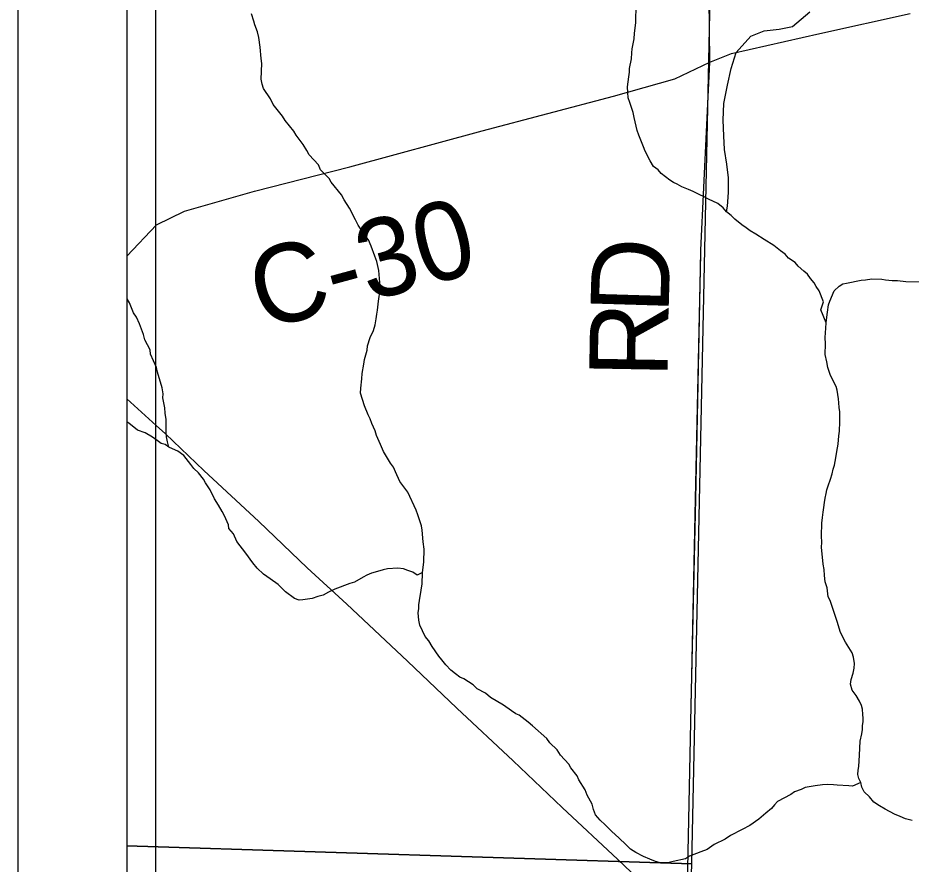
# Model space of a CAD drawing. Extents: x 0 to 34, y -2.3 to 22.
# Drawn here: x 2 to 2.648, y 15.492 to 16.107 of the extents above; entities that cross this region are included whole.
import ezdxf

# ---------------------------------------------------------------- set-up
doc = ezdxf.new("R2010")
doc.units = 0
for name, color, linetype in [('GM_X_County', 7, 'Continuous'), ('GM_X_County_Road', 7, 'Continuous'), ('GM_X_County_Road_Text', 7, 'Continuous'), ('GM_X_Minor_River', 7, 'Continuous'), ('GM_X_Section', 7, 'Continuous'), ('GM_X_State_Route', 7, 'Continuous'), ('GM_X_Township', 7, 'Continuous'), ('GM_X_Township_Road', 7, 'Continuous'), ('GM_X_Township_Road_Text', 7, 'Continuous'), ('SH_Data', 7, 'Continuous')]:
    doc.layers.add(name, color=color, linetype=linetype)

msp = doc.modelspace()

# ---------------------------------------------------------------- linework, layer by layer
at = {"layer": 'GM_X_County'}
msp.add_line((2.07917, 20.89939), (2.07917, 14.49705), dxfattribs=at)
at = {"layer": 'GM_X_County_Road'}
for p, q in [((2.58209, 16.09537), (2.64769, 16.10984)), ((2.51807, 16.0809), (2.58209, 16.09537)), ((2.50234, 16.0746), (2.51807, 16.0809)), ((2.47701, 16.06249), (2.50234, 16.0746)), ((2.43234, 16.04975), (2.47701, 16.06249)), ((2.33701, 16.02474), (2.43234, 16.04975)), ((2.24106, 15.99863), (2.33701, 16.02474)), ((2.17184, 15.98085), (2.24106, 15.99863)), ((2.12104, 15.96622), (2.17184, 15.98085)), ((2.10074, 15.95631), (2.12104, 15.96622)), ((2.07917, 15.93367), (2.10074, 15.95631))]:
    msp.add_line(p, q, dxfattribs=at)
at = {"layer": 'GM_X_Minor_River'}
for p, q in [((2.44859, 16.10618), (2.44901, 16.12099)), ((2.17141, 16.10421), (2.16967, 16.10958)), ((2.56232, 16.10048), (2.5748, 16.11115)), ((2.17209, 16.10153), (2.17141, 16.10421)), ((2.17385, 16.09654), (2.17209, 16.10153)), ((2.44752, 16.09558), (2.4485, 16.10315)), ((2.4485, 16.10315), (2.44859, 16.10618)), ((2.17487, 16.09233), (2.17385, 16.09654)), ((2.4474, 16.0914), (2.44752, 16.09558)), ((2.53209, 16.09338), (2.54171, 16.09728)), ((2.54171, 16.09728), (2.55276, 16.09848)), ((2.55276, 16.09848), (2.56232, 16.10048)), ((2.17581, 16.08546), (2.17487, 16.09233)), ((2.44605, 16.08423), (2.4474, 16.0914)), ((2.52148, 16.08152), (2.53209, 16.09338)), ((2.17671, 16.07708), (2.17581, 16.08546)), ((2.44558, 16.0812), (2.44605, 16.08423)), ((2.51772, 16.06985), (2.52148, 16.08152)), ((2.17699, 16.07365), (2.17671, 16.07708)), ((2.44411, 16.06985), (2.44546, 16.07703)), ((2.44546, 16.07703), (2.44558, 16.0812)), ((2.17666, 16.06226), (2.17699, 16.07365)), ((2.44404, 16.06719), (2.44411, 16.06985)), ((2.51509, 16.05775), (2.51772, 16.06985)), ((2.17731, 16.05845), (2.17666, 16.06226)), ((2.44259, 16.0566), (2.44356, 16.06379)), ((2.44356, 16.06379), (2.44404, 16.06719)), ((2.17836, 16.05538), (2.17731, 16.05845)), ((2.18347, 16.048), (2.17836, 16.05538)), ((2.44285, 16.05241), (2.44259, 16.0566)), ((2.51242, 16.04452), (2.51509, 16.05775)), ((2.44312, 16.0486), (2.44285, 16.05241)), ((2.18525, 16.04377), (2.18347, 16.048)), ((2.19222, 16.03521), (2.18525, 16.04377)), ((2.44416, 16.04516), (2.44312, 16.0486)), ((2.44661, 16.03786), (2.44416, 16.04516)), ((2.51206, 16.03236), (2.51242, 16.04452)), ((2.44727, 16.03443), (2.44661, 16.03786)), ((2.19403, 16.03211), (2.19222, 16.03521)), ((2.20027, 16.02433), (2.19403, 16.03211)), ((2.44965, 16.02486), (2.44727, 16.03443)), ((2.51249, 16.02094), (2.51206, 16.03236)), ((2.20209, 16.02162), (2.20027, 16.02433)), ((2.45069, 16.02141), (2.44965, 16.02486)), ((2.20721, 16.01463), (2.20209, 16.02162)), ((2.45425, 16.01294), (2.45069, 16.02141)), ((2.51296, 16.01104), (2.51249, 16.02094)), ((2.20975, 16.01037), (2.20721, 16.01463)), ((2.21156, 16.00728), (2.20975, 16.01037)), ((2.4553, 16.00987), (2.45425, 16.01294)), ((2.51455, 16.00035), (2.51296, 16.01104)), ((2.21819, 15.99986), (2.21156, 16.00728)), ((2.4589, 16.00293), (2.4553, 16.00987)), ((2.21961, 15.9964), (2.21819, 15.99986)), ((2.46144, 15.99867), (2.4589, 16.00293)), ((2.46479, 15.99629), (2.46144, 15.99867)), ((2.51578, 15.99042), (2.51455, 16.00035)), ((2.22589, 15.99014), (2.21961, 15.9964)), ((2.46699, 15.99357), (2.46479, 15.99629)), ((2.47332, 15.98882), (2.46699, 15.99357)), ((2.22733, 15.98743), (2.22589, 15.99014)), ((2.23504, 15.97809), (2.22733, 15.98743)), ((2.47593, 15.98722), (2.47332, 15.98882)), ((2.47856, 15.98601), (2.47593, 15.98722)), ((2.48192, 15.98401), (2.47856, 15.98601)), ((2.4868, 15.98196), (2.48192, 15.98401)), ((2.51584, 15.97977), (2.51578, 15.99042)), ((2.23684, 15.97461), (2.23504, 15.97809)), ((2.49019, 15.98072), (2.4868, 15.98196)), ((2.49506, 15.9783), (2.49019, 15.98072)), ((2.49769, 15.97708), (2.49506, 15.9783)), ((2.51518, 15.9699), (2.51584, 15.97977)), ((2.24085, 15.96842), (2.23684, 15.97461)), ((2.50143, 15.97507), (2.49769, 15.97708)), ((2.50818, 15.97183), (2.50143, 15.97507)), ((2.51189, 15.96868), (2.50818, 15.97183)), ((2.24516, 15.95993), (2.24085, 15.96842)), ((2.51447, 15.96594), (2.51189, 15.96868)), ((2.51447, 15.96594), (2.51518, 15.9699)), ((2.51781, 15.96318), (2.51447, 15.96594)), ((2.24695, 15.95608), (2.24516, 15.95993)), ((2.52039, 15.96045), (2.51781, 15.96318)), ((2.5256, 15.95649), (2.52039, 15.96045)), ((2.25205, 15.94833), (2.24695, 15.95608)), ((2.52857, 15.95412), (2.5256, 15.95649)), ((2.53156, 15.95214), (2.52857, 15.95412)), ((2.53567, 15.94973), (2.53156, 15.95214)), ((2.25463, 15.94559), (2.25205, 15.94833)), ((2.2564, 15.94098), (2.25463, 15.94559)), ((2.54164, 15.94575), (2.53567, 15.94973)), ((2.54873, 15.94136), (2.54164, 15.94575)), ((2.25923, 15.93368), (2.2564, 15.94098)), ((2.55356, 15.93742), (2.54873, 15.94136)), ((2.26064, 15.92984), (2.25923, 15.93368)), ((2.55691, 15.93504), (2.55356, 15.93742)), ((2.55949, 15.93231), (2.55691, 15.93504)), ((2.56434, 15.92912), (2.55949, 15.93231)), ((2.26197, 15.92334), (2.26064, 15.92984)), ((2.56655, 15.9264), (2.56434, 15.92912)), ((2.57062, 15.92285), (2.56655, 15.9264)), ((2.26286, 15.91457), (2.26197, 15.92334)), ((2.57322, 15.9205), (2.57062, 15.92285)), ((2.57541, 15.91739), (2.57322, 15.9205)), ((2.26265, 15.90736), (2.26286, 15.91457)), ((2.57798, 15.91428), (2.57541, 15.91739)), ((2.57942, 15.91158), (2.57798, 15.91428)), ((2.59616, 15.91184), (2.59887, 15.91366)), ((2.59887, 15.91366), (2.60154, 15.91396)), ((2.60154, 15.91396), (2.61225, 15.91629)), ((2.61225, 15.91629), (2.6153, 15.91658)), ((2.6153, 15.91658), (2.61988, 15.91721)), ((2.61988, 15.91721), (2.62709, 15.91699)), ((2.62709, 15.91699), (2.62974, 15.91653)), ((2.62974, 15.91653), (2.63467, 15.916)), ((2.63467, 15.916), (2.63847, 15.91589)), ((2.63847, 15.91589), (2.64453, 15.91533)), ((2.64453, 15.91533), (2.65783, 15.91493)), ((2.26218, 15.90434), (2.26265, 15.90736)), ((2.58161, 15.90847), (2.57942, 15.91158)), ((2.5848, 15.9004), (2.58161, 15.90847)), ((2.58938, 15.90102), (2.59264, 15.90852)), ((2.59264, 15.90852), (2.59616, 15.91184)), ((2.07929, 15.90259), (2.07917, 15.90274)), ((2.08111, 15.89987), (2.07929, 15.90259)), ((2.08394, 15.89257), (2.08111, 15.89987)), ((2.26114, 15.89449), (2.2617, 15.90093)), ((2.2617, 15.90093), (2.26218, 15.90434)), ((2.58293, 15.89466), (2.5848, 15.9004)), ((2.58854, 15.89839), (2.58938, 15.90102)), ((2.26067, 15.89147), (2.26114, 15.89449)), ((2.58664, 15.88515), (2.58293, 15.89466)), ((2.58763, 15.8931), (2.58854, 15.89839)), ((2.08613, 15.88947), (2.08394, 15.89257)), ((2.08827, 15.88446), (2.08613, 15.88947)), ((2.25931, 15.88391), (2.26019, 15.88806)), ((2.26019, 15.88806), (2.26067, 15.89147)), ((2.58664, 15.88515), (2.58714, 15.88931)), ((2.58714, 15.88931), (2.58763, 15.8931)), ((2.09108, 15.87678), (2.08827, 15.88446)), ((2.25805, 15.87977), (2.25931, 15.88391)), ((2.58595, 15.87453), (2.58653, 15.88135)), ((2.58653, 15.88135), (2.58664, 15.88515)), ((2.09211, 15.87295), (2.09108, 15.87678)), ((2.25392, 15.8685), (2.25562, 15.87453)), ((2.25562, 15.87453), (2.25805, 15.87977)), ((2.5862, 15.86997), (2.58595, 15.87453)), ((2.09608, 15.86562), (2.09211, 15.87295)), ((2.25345, 15.86547), (2.25392, 15.8685)), ((2.58598, 15.86238), (2.5862, 15.86997)), ((2.09638, 15.86257), (2.09608, 15.86562)), ((2.10066, 15.85294), (2.09638, 15.86257)), ((2.25174, 15.85868), (2.25345, 15.86547)), ((2.58735, 15.85702), (2.58598, 15.86238)), ((2.24992, 15.84848), (2.25126, 15.85528)), ((2.25126, 15.85528), (2.25174, 15.85868)), ((2.58799, 15.85282), (2.58735, 15.85702)), ((2.10132, 15.8495), (2.10066, 15.85294)), ((2.10479, 15.838), (2.10132, 15.8495)), ((2.24981, 15.84469), (2.24992, 15.84848)), ((2.58974, 15.84783), (2.58799, 15.85282)), ((2.5908, 15.84514), (2.58974, 15.84783)), ((2.24885, 15.83788), (2.24981, 15.84469)), ((2.59405, 15.83896), (2.5908, 15.84514)), ((2.10543, 15.83381), (2.10479, 15.838)), ((2.24875, 15.83408), (2.24885, 15.83788)), ((2.59473, 15.83628), (2.59405, 15.83896)), ((2.59569, 15.83018), (2.59473, 15.83628)), ((2.10534, 15.83077), (2.10543, 15.83381)), ((2.10665, 15.82351), (2.10534, 15.83077)), ((2.25152, 15.82488), (2.24875, 15.83408)), ((2.59598, 15.82713), (2.59569, 15.83018)), ((2.10692, 15.81971), (2.10665, 15.82351)), ((2.25437, 15.81834), (2.25152, 15.82488)), ((2.59627, 15.8237), (2.59598, 15.82713)), ((2.59656, 15.82065), (2.59627, 15.8237)), ((2.10755, 15.81513), (2.10692, 15.81971)), ((2.25581, 15.81564), (2.25437, 15.81834)), ((2.25686, 15.81219), (2.25581, 15.81564)), ((2.59673, 15.81343), (2.59656, 15.82065)), ((2.08048, 15.81252), (2.07917, 15.81327)), ((2.0868, 15.80739), (2.08048, 15.81252)), ((2.10776, 15.80942), (2.10755, 15.81513)), ((2.10766, 15.80601), (2.10776, 15.80942)), ((2.25936, 15.80679), (2.25686, 15.81219)), ((2.59653, 15.8066), (2.59673, 15.81343)), ((2.09244, 15.80532), (2.0868, 15.80739)), ((2.09767, 15.80213), (2.09244, 15.80532)), ((2.10795, 15.80258), (2.10766, 15.80601)), ((2.1086, 15.79876), (2.10795, 15.80258)), ((2.2604, 15.80334), (2.25936, 15.80679)), ((2.26325, 15.7968), (2.2604, 15.80334)), ((2.5955, 15.79713), (2.59605, 15.80319)), ((2.59605, 15.80319), (2.59653, 15.8066)), ((2.10102, 15.79975), (2.09767, 15.80213)), ((2.104, 15.79776), (2.10102, 15.79975)), ((2.10702, 15.79691), (2.104, 15.79776)), ((2.10963, 15.79493), (2.10702, 15.79691)), ((2.10963, 15.79493), (2.1086, 15.79876)), ((2.26539, 15.7918), (2.26325, 15.7968)), ((2.59458, 15.79184), (2.5955, 15.79713)), ((2.11225, 15.79371), (2.10963, 15.79493)), ((2.11601, 15.79208), (2.11225, 15.79371)), ((2.12047, 15.78891), (2.11601, 15.79208)), ((2.27046, 15.78329), (2.26539, 15.7918)), ((2.59369, 15.78731), (2.59458, 15.79184)), ((2.12561, 15.7823), (2.12047, 15.78891)), ((2.27267, 15.78056), (2.27046, 15.78329)), ((2.59278, 15.78202), (2.59324, 15.78466)), ((2.59324, 15.78466), (2.59369, 15.78731)), ((2.12781, 15.77957), (2.12561, 15.7823)), ((2.13114, 15.77643), (2.12781, 15.77957)), ((2.27409, 15.7771), (2.27267, 15.78056)), ((2.27731, 15.77017), (2.27409, 15.7771)), ((2.59107, 15.77561), (2.59193, 15.779)), ((2.59193, 15.779), (2.59278, 15.78202)), ((2.13481, 15.77177), (2.13114, 15.77643)), ((2.13625, 15.76906), (2.13481, 15.77177)), ((2.28317, 15.76239), (2.27731, 15.77017)), ((2.58816, 15.76696), (2.58982, 15.77185)), ((2.58982, 15.77185), (2.59107, 15.77561)), ((2.13952, 15.76403), (2.13625, 15.76906)), ((2.14276, 15.75747), (2.13952, 15.76403)), ((2.58686, 15.7613), (2.58732, 15.76395)), ((2.58732, 15.76395), (2.58816, 15.76696)), ((2.14566, 15.75283), (2.14276, 15.75747)), ((2.28925, 15.7493), (2.28317, 15.76239)), ((2.58553, 15.75488), (2.586, 15.75791)), ((2.586, 15.75791), (2.58686, 15.7613)), ((2.14819, 15.74819), (2.14566, 15.75283)), ((2.58457, 15.74769), (2.58504, 15.7511)), ((2.58504, 15.7511), (2.58553, 15.75488)), ((2.15, 15.7451), (2.14819, 15.74819)), ((2.15285, 15.73856), (2.15, 15.7451)), ((2.29029, 15.74585), (2.28925, 15.7493)), ((2.2931, 15.73778), (2.29029, 15.74585)), ((2.58407, 15.74391), (2.58457, 15.74769)), ((2.15316, 15.73589), (2.15285, 15.73856)), ((2.29339, 15.73474), (2.2931, 15.73778)), ((2.58331, 15.73063), (2.58357, 15.73975)), ((2.58357, 15.73975), (2.58407, 15.74391)), ((2.15646, 15.73199), (2.15316, 15.73589)), ((2.15897, 15.7266), (2.15646, 15.73199)), ((2.29429, 15.72635), (2.29339, 15.73474)), ((2.16556, 15.71804), (2.15897, 15.7266)), ((2.29489, 15.72101), (2.29429, 15.72635)), ((2.58355, 15.72569), (2.58331, 15.73063)), ((2.58345, 15.72227), (2.58355, 15.72569)), ((2.29462, 15.71153), (2.29489, 15.72101)), ((2.58462, 15.71008), (2.58345, 15.72227)), ((2.17068, 15.71105), (2.16556, 15.71804)), ((2.17361, 15.70716), (2.17068, 15.71105)), ((2.17843, 15.70284), (2.17361, 15.70716)), ((2.26519, 15.70595), (2.25944, 15.70422)), ((2.26825, 15.70661), (2.26519, 15.70595)), ((2.27587, 15.70715), (2.26825, 15.70661)), ((2.28003, 15.70664), (2.27587, 15.70715)), ((2.28304, 15.70542), (2.28003, 15.70664)), ((2.28681, 15.70416), (2.28304, 15.70542)), ((2.29364, 15.70396), (2.29462, 15.71153)), ((2.58527, 15.70626), (2.58462, 15.71008)), ((2.58552, 15.7017), (2.58527, 15.70626)), ((2.18327, 15.69928), (2.17843, 15.70284)), ((2.18886, 15.69531), (2.18327, 15.69928)), ((2.25059, 15.70068), (2.24441, 15.69707)), ((2.2533, 15.70212), (2.25059, 15.70068)), ((2.25676, 15.70354), (2.2533, 15.70212)), ((2.25944, 15.70422), (2.25676, 15.70354)), ((2.28979, 15.70217), (2.28681, 15.70416)), ((2.29364, 15.70396), (2.28979, 15.70217)), ((2.2934, 15.69561), (2.29364, 15.70396)), ((2.58614, 15.69712), (2.58552, 15.7017)), ((2.1944, 15.68983), (2.18886, 15.69531)), ((2.24096, 15.69603), (2.23019, 15.6918)), ((2.24441, 15.69707), (2.24096, 15.69603)), ((2.29247, 15.68956), (2.29295, 15.69296)), ((2.29295, 15.69296), (2.2934, 15.69561)), ((2.58754, 15.6929), (2.58614, 15.69712)), ((2.58812, 15.68642), (2.58754, 15.6929)), ((2.20073, 15.68508), (2.1944, 15.68983)), ((2.21787, 15.68647), (2.21365, 15.68507)), ((2.2217, 15.68749), (2.21787, 15.68647)), ((2.22557, 15.68966), (2.2217, 15.68749)), ((2.23019, 15.6918), (2.22557, 15.68966)), ((2.29106, 15.68048), (2.29201, 15.68691)), ((2.29201, 15.68691), (2.29247, 15.68956)), ((2.58956, 15.68372), (2.58812, 15.68642)), ((2.20411, 15.68384), (2.20073, 15.68508)), ((2.20678, 15.68414), (2.20411, 15.68384)), ((2.21365, 15.68507), (2.20678, 15.68414)), ((2.29099, 15.67782), (2.29106, 15.68048)), ((2.59201, 15.67643), (2.58956, 15.68372)), ((2.29052, 15.6748), (2.29099, 15.67782)), ((2.29113, 15.66946), (2.29052, 15.6748)), ((2.59482, 15.66837), (2.59201, 15.67643)), ((2.29178, 15.66564), (2.29113, 15.66946)), ((2.59725, 15.66032), (2.59482, 15.66837)), ((2.29572, 15.65755), (2.29178, 15.66564)), ((2.60085, 15.65337), (2.59725, 15.66032)), ((2.29829, 15.65443), (2.29572, 15.65755)), ((2.30083, 15.65018), (2.29829, 15.65443)), ((2.60557, 15.64564), (2.60085, 15.65337)), ((2.30557, 15.6432), (2.30083, 15.65018)), ((2.30778, 15.64047), (2.30557, 15.6432)), ((2.31071, 15.63697), (2.30778, 15.64047)), ((2.60662, 15.64257), (2.60557, 15.64564)), ((2.60724, 15.63799), (2.60662, 15.64257)), ((2.3144, 15.63306), (2.31071, 15.63697)), ((2.60628, 15.6308), (2.60715, 15.63457)), ((2.60715, 15.63457), (2.60724, 15.63799)), ((2.31775, 15.6303), (2.3144, 15.63306)), ((2.32072, 15.62793), (2.31775, 15.6303)), ((2.32372, 15.6267), (2.32072, 15.62793)), ((2.605, 15.62628), (2.60628, 15.6308)), ((2.32709, 15.6247), (2.32372, 15.6267)), ((2.33044, 15.62232), (2.32709, 15.6247)), ((2.3334, 15.61957), (2.33044, 15.62232)), ((2.60453, 15.62287), (2.605, 15.62628)), ((2.60554, 15.61866), (2.60453, 15.62287)), ((2.33939, 15.61635), (2.3334, 15.61957)), ((2.3431, 15.6132), (2.33939, 15.61635)), ((2.60847, 15.61478), (2.60554, 15.61866)), ((2.61101, 15.61052), (2.60847, 15.61478)), ((2.35244, 15.60761), (2.3431, 15.6132)), ((2.61244, 15.60744), (2.61101, 15.61052)), ((2.35841, 15.60363), (2.35244, 15.60761)), ((2.36138, 15.60126), (2.35841, 15.60363)), ((2.61313, 15.60476), (2.61244, 15.60744)), ((2.6134, 15.60095), (2.61313, 15.60476)), ((2.36402, 15.60042), (2.36138, 15.60126)), ((2.37033, 15.59529), (2.36402, 15.60042)), ((2.37367, 15.59254), (2.37033, 15.59529)), ((2.61317, 15.59298), (2.61362, 15.59563)), ((2.6137, 15.59828), (2.6134, 15.60095)), ((2.61362, 15.59563), (2.6137, 15.59828)), ((2.38406, 15.58349), (2.37367, 15.59254)), ((2.61261, 15.58692), (2.61308, 15.58994)), ((2.61308, 15.58994), (2.61317, 15.59298)), ((2.38625, 15.58038), (2.38406, 15.58349)), ((2.61132, 15.58164), (2.61261, 15.58692)), ((2.39142, 15.57529), (2.38625, 15.58038)), ((2.61102, 15.57139), (2.61132, 15.58164)), ((2.39397, 15.57142), (2.39142, 15.57529)), ((2.39986, 15.56478), (2.39397, 15.57142)), ((2.6104, 15.56305), (2.61102, 15.57139)), ((2.4013, 15.56208), (2.39986, 15.56478)), ((2.60995, 15.56041), (2.6104, 15.56305)), ((2.40608, 15.55624), (2.4013, 15.56208)), ((2.40714, 15.55355), (2.40608, 15.55624)), ((2.60986, 15.55737), (2.60995, 15.56041)), ((2.61053, 15.55431), (2.60986, 15.55737)), ((2.41187, 15.54619), (2.40714, 15.55355)), ((2.58417, 15.54978), (2.57883, 15.54918)), ((2.58798, 15.55004), (2.58417, 15.54978)), ((2.59216, 15.54992), (2.58798, 15.55004)), ((2.59481, 15.54946), (2.59216, 15.54992)), ((2.61197, 15.55161), (2.60581, 15.54875)), ((2.61197, 15.55161), (2.61053, 15.55431)), ((2.61263, 15.54817), (2.61197, 15.55161)), ((2.41328, 15.54235), (2.41187, 15.54619)), ((2.56388, 15.54469), (2.56116, 15.54287)), ((2.56849, 15.54645), (2.56388, 15.54469)), ((2.57157, 15.54788), (2.56849, 15.54645)), ((2.57577, 15.54851), (2.57157, 15.54788)), ((2.57883, 15.54918), (2.57577, 15.54851)), ((2.60316, 15.54921), (2.59481, 15.54946)), ((2.60581, 15.54875), (2.60316, 15.54921)), ((2.61443, 15.5447), (2.61263, 15.54817)), ((2.61813, 15.54117), (2.61443, 15.5447)), ((2.41689, 15.53578), (2.41328, 15.54235)), ((2.55151, 15.53784), (2.54916, 15.53525)), ((2.56116, 15.54287), (2.55151, 15.53784)), ((2.62144, 15.53727), (2.61813, 15.54117)), ((2.62554, 15.53449), (2.62144, 15.53727)), ((2.41792, 15.53195), (2.41689, 15.53578)), ((2.41933, 15.52811), (2.41792, 15.53195)), ((2.54718, 15.53265), (2.54291, 15.52936)), ((2.54916, 15.53525), (2.54718, 15.53265)), ((2.62965, 15.53208), (2.62554, 15.53449)), ((2.63639, 15.52846), (2.62965, 15.53208)), ((2.42264, 15.52421), (2.41933, 15.52811)), ((2.42634, 15.52068), (2.42264, 15.52421)), ((2.53784, 15.52495), (2.53124, 15.52021)), ((2.54291, 15.52936), (2.53784, 15.52495)), ((2.64053, 15.52682), (2.63639, 15.52846)), ((2.64428, 15.52519), (2.64053, 15.52682)), ((2.64918, 15.5239), (2.64428, 15.52519)), ((2.43114, 15.51598), (2.42634, 15.52068)), ((2.52583, 15.51733), (2.51735, 15.51302)), ((2.53124, 15.52021), (2.52583, 15.51733)), ((2.43633, 15.51127), (2.43114, 15.51598)), ((2.4415, 15.50617), (2.43633, 15.51127)), ((2.51735, 15.51302), (2.51347, 15.51048)), ((2.44484, 15.50303), (2.4415, 15.50617)), ((2.50538, 15.50654), (2.50033, 15.5029)), ((2.51347, 15.51048), (2.50538, 15.50654)), ((2.44857, 15.50064), (2.44484, 15.50303)), ((2.45419, 15.49782), (2.44857, 15.50064)), ((2.45869, 15.49578), (2.45419, 15.49782)), ((2.48764, 15.49796), (2.48455, 15.49615)), ((2.49572, 15.50114), (2.48764, 15.49796)), ((2.50033, 15.5029), (2.49572, 15.50114)), ((2.46282, 15.49414), (2.45869, 15.49578)), ((2.4666, 15.49327), (2.46282, 15.49414)), ((2.47192, 15.49311), (2.4666, 15.49327)), ((2.47575, 15.49413), (2.47192, 15.49311)), ((2.48455, 15.49615), (2.47575, 15.49413))]:
    msp.add_line(p, q, dxfattribs=at)
at = {"layer": 'GM_X_Section'}
for p, q in [((2.07917, 16.50156), (2.07917, 15.50545)), ((2.48913, 15.49252), (2.50896, 16.41908)), ((2.48913, 15.49252), (2.50896, 16.41908)), ((2.07917, 15.50545), (2.07917, 14.50598)), ((2.07917, 15.50545), (2.48913, 15.49252)), ((2.48913, 15.49252), (2.07917, 15.50545)), ((2.48719, 15.41263), (2.48913, 15.49252)), ((2.48719, 15.41263), (2.48913, 15.49252))]:
    msp.add_line(p, q, dxfattribs=at)
at = {"layer": 'GM_X_State_Route'}
for p, q in [((2.07917, 15.83015), (2.10045, 15.81076)), ((2.10045, 15.81076), (2.10719, 15.80463)), ((2.10719, 15.80463), (2.13488, 15.77801)), ((2.13488, 15.77801), (2.17503, 15.74109)), ((2.17503, 15.74109), (2.21007, 15.7074)), ((2.21007, 15.7074), (2.23892, 15.68106)), ((2.23892, 15.68106), (2.28274, 15.63956)), ((2.28274, 15.63956), (2.31876, 15.60551)), ((2.31876, 15.60551), (2.35954, 15.56716)), ((2.35954, 15.56716), (2.39502, 15.53338)), ((2.39502, 15.53338), (2.43544, 15.49556)), ((2.43544, 15.49556), (2.46259, 15.47011))]:
    msp.add_line(p, q, dxfattribs=at)
at = {"layer": 'GM_X_Township'}
for p, q in [((2.07917, 20.46698), (2.07917, 14.49705)), ((2.50234, 16.0746), (2.50159, 16.14175)), ((2.50234, 16.0746), (2.50159, 16.14175)), ((2.49571, 15.93808), (2.50234, 16.0746)), ((2.49571, 15.93808), (2.50234, 16.0746)), ((2.49543, 15.92419), (2.49571, 15.93808)), ((2.49543, 15.92419), (2.49571, 15.93808)), ((2.49203, 15.75753), (2.49543, 15.92419)), ((2.49203, 15.75753), (2.49543, 15.92419)), ((2.48885, 15.60716), (2.49203, 15.75753)), ((2.48885, 15.60716), (2.49203, 15.75753)), ((2.4855, 15.44815), (2.48885, 15.60716)), ((2.4855, 15.44815), (2.48885, 15.60716))]:
    msp.add_line(p, q, dxfattribs=at)
at = {"layer": 'GM_X_Township_Road'}
for p, q in [((2.50234, 16.0746), (2.50159, 16.14175)), ((2.49571, 15.93807), (2.50234, 16.0746)), ((2.49543, 15.92419), (2.49566, 15.93549)), ((2.49566, 15.93549), (2.49571, 15.93807)), ((2.49202, 15.75753), (2.49543, 15.92419)), ((2.48906, 15.61723), (2.49202, 15.75753)), ((2.48885, 15.60716), (2.48906, 15.61723)), ((2.4855, 15.44815), (2.48885, 15.60716))]:
    msp.add_line(p, q, dxfattribs=at)
at = {"layer": 'SH_Data'}
for p, q in [((2, 21), (2, 14)), ((2.1, 20.9), (2.1, 14.1))]:
    msp.add_line(p, q, dxfattribs=at)

# ---------------------------------------------------------------- texts
at = {"layer": 'GM_X_County_Road_Text'}
msp.add_text('C-30', height=0.056818, rotation=15.1583, dxfattribs=at).set_placement((2.17735, 15.87976))
at = {"layer": 'GM_X_Township_Road_Text'}
for s, rotation, p in [('D', 88.28307, (2.47231, 15.89138)), ('R', 88.97344, (2.47147, 15.84491))]:
    msp.add_text(s, height=0.05682, rotation=rotation, dxfattribs=at).set_placement(p)

doc.saveas('drawing.dxf')
